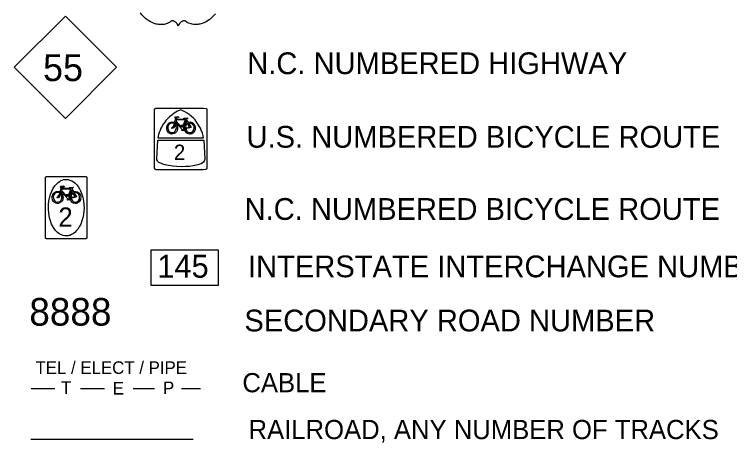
# Model space of a CAD drawing. Extents: x 5197761 to 5514561, y 1890130 to 2080942.
# Drawn here: x 5485887 to 5504538, y 2029224 to 2040388 of the extents above; entities that cross this region are included whole.
import ezdxf

# ---------------------------------------------------------------- set-up
doc = ezdxf.new("R2010")
doc.units = 0
for name, color, linetype in [('Exist Railroad Mainline', 7, 'Continuous'), ('Exist Railroad Mainline Label', 7, 'Continuous'), ('Exist Road Primary Interstate Interchange CELL', 7, 'Continuous'), ('Exist Road Primary Interstate Label', 7, 'Continuous'), ('Exist Road Primary NC Shield Bike CELL', 7, 'Continuous'), ('Exist Road Primary NC Shield CELL', 7, 'Continuous'), ('Exist Road Primary NC Shield Number Label', 7, 'Continuous'), ('Exist Road Primary US Shield Bike CELL', 7, 'Continuous'), ('Exist Road Primary US Shield CELL', 7, 'Continuous'), ('Exist Road Primary US Shield Number Label', 7, 'Continuous'), ('Exist Road Secondary Type 51 Label', 7, 'Continuous'), ('Exist Road Secondary Type 51 Number Label', 7, 'Continuous'), ('Exist Utilities Electrical Transmission Line', 7, 'Continuous'), ('Exist Utilities Electrical Transmission Line Label', 7, 'Continuous')]:
    doc.layers.add(name, color=color, linetype=linetype)

msp = doc.modelspace()

# ---------------------------------------------------------------- linework, layer by layer
at = {"layer": 'Exist Railroad Mainline'}
msp.add_line((5490548, 2029308), (5486316, 2029308), dxfattribs=at)
at = {"layer": 'Exist Road Primary Interstate Interchange CELL'}
msp.add_lwpolyline([(5489459, 2034253), (5491199, 2034253), (5491199, 2033320), (5489459, 2033320)], close=True, dxfattribs=at)
at = {"layer": 'Exist Road Primary NC Shield Bike CELL'}
for points in [[(5486738, 2036164), (5486741, 2036164), (5486873, 2036164), (5487606, 2036164), (5487739, 2036164), (5487743, 2036163), (5487746, 2036163), (5487749, 2036162), (5487752, 2036161), (5487755, 2036160), (5487760, 2036158), (5487762, 2036156), (5487765, 2036154), (5487768, 2036152), (5487771, 2036148), (5487774, 2036145), (5487775, 2036143), (5487776, 2036141), (5487777, 2036139), (5487778, 2036138), (5487779, 2036136), (5487780, 2036133), (5487781, 2036129), (5487781, 2036126), (5487781, 2036124), (5487781, 2036123), (5487781, 2035989), (5487781, 2034709), (5487781, 2034577), (5487781, 2034572), (5487781, 2034570), (5487780, 2034567), (5487779, 2034564), (5487778, 2034561), (5487776, 2034556), (5487774, 2034553), (5487772, 2034551), (5487770, 2034548), (5487768, 2034546), (5487766, 2034544), (5487764, 2034543), (5487762, 2034541), (5487761, 2034540), (5487759, 2034540), (5487757, 2034538), (5487754, 2034537), (5487751, 2034536), (5487747, 2034535), (5487745, 2034535), (5487743, 2034534), (5487742, 2034534), (5487740, 2034534), (5487738, 2034534), (5487606, 2034534), (5486873, 2034534), (5486741, 2034534), (5486738, 2034534), (5486736, 2034534), (5486734, 2034535), (5486731, 2034535), (5486728, 2034536), (5486725, 2034537), (5486722, 2034539), (5486720, 2034540), (5486717, 2034541), (5486715, 2034543), (5486713, 2034544), (5486712, 2034546), (5486711, 2034547), (5486709, 2034549), (5486708, 2034550), (5486706, 2034552), (5486705, 2034554), (5486704, 2034556), (5486703, 2034558), (5486702, 2034560), (5486701, 2034562), (5486701, 2034563), (5486700, 2034564), (5486700, 2034565), (5486700, 2034566), (5486699, 2034567), (5486699, 2034568), (5486699, 2034569), (5486699, 2034570), (5486699, 2034571), (5486698, 2034572), (5486698, 2034573), (5486698, 2034574), (5486698, 2034576), (5486698, 2034709), (5486698, 2035989), (5486698, 2036121), (5486698, 2036126), (5486699, 2036128), (5486699, 2036131), (5486700, 2036134), (5486701, 2036137), (5486704, 2036142), (5486706, 2036145), (5486707, 2036147), (5486710, 2036150), (5486714, 2036154), (5486717, 2036156), (5486719, 2036157), (5486720, 2036158), (5486722, 2036159), (5486724, 2036160), (5486726, 2036161), (5486729, 2036162), (5486733, 2036163), (5486736, 2036163)], [(5487240, 2034612), (5487221, 2034613), (5487203, 2034614), (5487164, 2034621), (5487119, 2034638), (5487093, 2034650), (5487071, 2034662), (5487049, 2034678), (5487017, 2034701), (5486962, 2034757), (5486908, 2034829), (5486860, 2034922), (5486827, 2035005), (5486806, 2035087), (5486784, 2035210), (5486776, 2035308), (5486776, 2035355), (5486777, 2035390), (5486778, 2035415), (5486781, 2035452), (5486786, 2035509), (5486797, 2035568), (5486805, 2035605), (5486810, 2035626), (5486821, 2035665), (5486831, 2035699), (5486863, 2035781), (5486902, 2035855), (5486945, 2035917), (5486983, 2035964), (5487029, 2036007), (5487065, 2036031), (5487083, 2036042), (5487104, 2036053), (5487139, 2036069), (5487180, 2036080), (5487218, 2036086), (5487248, 2036086), (5487292, 2036082), (5487337, 2036070), (5487389, 2036047), (5487434, 2036019), (5487474, 2035986), (5487516, 2035942), (5487551, 2035897), (5487585, 2035841), (5487614, 2035787), (5487642, 2035718), (5487665, 2035646), (5487681, 2035577), (5487693, 2035511), (5487699, 2035453), (5487701, 2035420), (5487705, 2035344), (5487701, 2035263), (5487690, 2035168), (5487673, 2035086), (5487650, 2035002), (5487618, 2034922), (5487582, 2034851), (5487548, 2034799), (5487512, 2034753), (5487468, 2034706), (5487426, 2034673), (5487381, 2034647), (5487335, 2034627), (5487307, 2034620), (5487290, 2034617), (5487277, 2034614), (5487261, 2034613)], [(5487318, 2035871), (5487414, 2035882), (5487421, 2035875), (5487415, 2035860), (5487392, 2035853), (5487385, 2035840), (5487426, 2035771), (5487484, 2035774), (5487535, 2035762), (5487580, 2035728), (5487602, 2035694), (5487612, 2035675), (5487619, 2035644), (5487621, 2035612), (5487617, 2035577), (5487609, 2035551), (5487595, 2035524), (5487581, 2035503), (5487554, 2035481), (5487530, 2035467), (5487496, 2035459), (5487475, 2035458), (5487432, 2035465), (5487404, 2035479), (5487391, 2035490), (5487370, 2035516), (5487356, 2035540), (5487338, 2035589), (5487334, 2035613), (5487363, 2035591), (5487386, 2035552), (5487403, 2035525), (5487424, 2035510), (5487457, 2035496), (5487481, 2035496), (5487514, 2035503), (5487544, 2035520), (5487566, 2035542), (5487583, 2035570), (5487589, 2035610), (5487588, 2035643), (5487580, 2035670), (5487566, 2035694), (5487552, 2035711), (5487528, 2035729), (5487505, 2035737), (5487468, 2035744), (5487442, 2035747), (5487512, 2035628), (5487363, 2035591), (5487334, 2035613), (5487470, 2035637), (5487413, 2035735), (5487374, 2035693), (5487363, 2035619), (5487334, 2035613), (5487335, 2035644), (5487348, 2035691), (5487369, 2035724), (5487400, 2035760), (5487381, 2035802), (5487306, 2035610), (5487334, 2035613), (5487338, 2035589), (5487304, 2035585), (5487311, 2035564), (5487332, 2035553), (5487281, 2035542), (5487269, 2035558), (5487287, 2035567), (5487108, 2035772), (5487101, 2035752), (5487126, 2035719), (5487143, 2035687), (5487154, 2035653), (5487159, 2035623), (5487156, 2035593), (5487148, 2035553), (5487128, 2035518), (5487101, 2035491), (5487070, 2035472), (5487031, 2035462), (5487003, 2035460), (5486975, 2035464), (5486926, 2035494), (5486910, 2035512), (5486887, 2035553), (5486877, 2035605), (5486876, 2035642), (5486886, 2035675), (5486900, 2035704), (5486917, 2035725), (5486941, 2035749), (5486962, 2035762), (5486990, 2035771), (5487018, 2035773), (5487079, 2035767), (5487093, 2035734), (5487074, 2035658), (5487050, 2035618), (5487015, 2035601), (5487001, 2035615), (5487058, 2035673), (5487070, 2035728), (5487057, 2035734), (5487033, 2035742), (5486995, 2035743), (5486973, 2035736), (5486944, 2035719), (5486915, 2035682), (5486903, 2035643), (5486908, 2035600), (5486919, 2035560), (5486933, 2035535), (5486953, 2035519), (5486982, 2035501), (5487008, 2035496), (5487040, 2035499), (5487071, 2035512), (5487098, 2035539), (5487115, 2035572), (5487125, 2035595), (5487128, 2035624), (5487124, 2035656), (5487109, 2035692), (5487079, 2035767), (5487110, 2035854), (5487131, 2035831), (5487120, 2035797), (5487262, 2035637), (5487258, 2035657), (5487243, 2035683), (5487250, 2035689), (5487291, 2035689), (5487283, 2035659), (5487287, 2035638), (5487363, 2035829), (5487131, 2035831), (5487110, 2035854), (5487083, 2035882), (5487106, 2035909), (5487167, 2035917), (5487192, 2035897), (5487179, 2035880), (5487141, 2035884), (5487116, 2035879), (5487122, 2035874), (5487135, 2035874), (5487129, 2035861), (5487366, 2035859), (5487367, 2035864)]]:
    msp.add_lwpolyline(points, close=True, dxfattribs=at)
at = {"layer": 'Exist Road Primary NC Shield CELL'}
msp.add_lwpolyline([(5485887, 2039007), (5487219, 2040339), (5488551, 2039007), (5487219, 2037675)], close=True, dxfattribs=at)
at = {"layer": 'Exist Road Primary US Shield Bike CELL'}
for points in [[(5489583, 2037942), (5489587, 2037942), (5489938, 2037942), (5490672, 2037942), (5490804, 2037942), (5490808, 2037942), (5490811, 2037941), (5490814, 2037941), (5490817, 2037940), (5490820, 2037939), (5490887, 2037936), (5490889, 2037935), (5490891, 2037933), (5490894, 2037930), (5490898, 2037926), (5490901, 2037923), (5490902, 2037921), (5490902, 2037920), (5490904, 2037918), (5490904, 2037916), (5490905, 2037914), (5490906, 2037911), (5490907, 2037908), (5490908, 2037904), (5490908, 2037903), (5490908, 2037901), (5490908, 2037767), (5490908, 2036488), (5490908, 2036382), (5490908, 2036377), (5490907, 2036375), (5490907, 2036372), (5490906, 2036369), (5490905, 2036366), (5490902, 2036360), (5490901, 2036358), (5490899, 2036356), (5490896, 2036353), (5490895, 2036351), (5490892, 2036349), (5490891, 2036348), (5490889, 2036346), (5490887, 2036345), (5490874, 2036340), (5490809, 2036339), (5490807, 2036339), (5490805, 2036339), (5490803, 2036339), (5490671, 2036339), (5489938, 2036339), (5489587, 2036339), (5489584, 2036339), (5489582, 2036339), (5489579, 2036340), (5489576, 2036340), (5489573, 2036341), (5489571, 2036342), (5489568, 2036344), (5489565, 2036345), (5489563, 2036346), (5489560, 2036348), (5489559, 2036349), (5489557, 2036351), (5489556, 2036352), (5489555, 2036354), (5489553, 2036355), (5489552, 2036357), (5489551, 2036359), (5489550, 2036360), (5489548, 2036363), (5489547, 2036365), (5489547, 2036367), (5489546, 2036368), (5489546, 2036369), (5489545, 2036370), (5489545, 2036371), (5489545, 2036372), (5489545, 2036373), (5489544, 2036374), (5489544, 2036375), (5489544, 2036376), (5489544, 2036377), (5489544, 2036378), (5489544, 2036379), (5489544, 2036381), (5489544, 2036487), (5489544, 2037767), (5489544, 2037899), (5489544, 2037904), (5489544, 2037906), (5489545, 2037909), (5489546, 2037912), (5489547, 2037915), (5489550, 2037921), (5489551, 2037923), (5489553, 2037925), (5489555, 2037928), (5489559, 2037932), (5489563, 2037935), (5489564, 2037936), (5489566, 2037936), (5489568, 2037938), (5489570, 2037938), (5489571, 2037939), (5489574, 2037940), (5489578, 2037941), (5489582, 2037942)], [(5490226, 2037902), (5490143, 2037865), (5490058, 2037812), (5489990, 2037762), (5489937, 2037720), (5489883, 2037665), (5489840, 2037617), (5489808, 2037577), (5489771, 2037521), (5489728, 2037449), (5489710, 2037417), (5489686, 2037357), (5489666, 2037307), (5489650, 2037256), (5489630, 2037170), (5490821, 2037170), (5490809, 2037221), (5490792, 2037287), (5490761, 2037370), (5490739, 2037418), (5490693, 2037503), (5490647, 2037572), (5490598, 2037634), (5490558, 2037678), (5490508, 2037726), (5490448, 2037776), (5490390, 2037816), (5490337, 2037848), (5490281, 2037876), (5490262, 2037885)], [(5490303, 2037679), (5490399, 2037690), (5490406, 2037683), (5490401, 2037668), (5490377, 2037661), (5490371, 2037648), (5490411, 2037579), (5490469, 2037582), (5490521, 2037571), (5490566, 2037536), (5490587, 2037502), (5490597, 2037484), (5490604, 2037453), (5490606, 2037420), (5490602, 2037386), (5490595, 2037360), (5490580, 2037332), (5490566, 2037312), (5490539, 2037290), (5490515, 2037276), (5490481, 2037267), (5490460, 2037266), (5490417, 2037273), (5490389, 2037287), (5490376, 2037298), (5490355, 2037324), (5490342, 2037349), (5490323, 2037397), (5490319, 2037421), (5490348, 2037400), (5490372, 2037360), (5490388, 2037333), (5490410, 2037318), (5490442, 2037305), (5490467, 2037304), (5490499, 2037312), (5490529, 2037329), (5490551, 2037350), (5490568, 2037378), (5490574, 2037419), (5490573, 2037451), (5490566, 2037478), (5490552, 2037503), (5490537, 2037520), (5490513, 2037538), (5490490, 2037545), (5490453, 2037552), (5490427, 2037555), (5490497, 2037437), (5490348, 2037400), (5490319, 2037421), (5490456, 2037446), (5490399, 2037543), (5490359, 2037501), (5490348, 2037427), (5490319, 2037421), (5490320, 2037452), (5490333, 2037499), (5490355, 2037532), (5490386, 2037568), (5490366, 2037610), (5490291, 2037418), (5490319, 2037421), (5490323, 2037397), (5490289, 2037393), (5490297, 2037373), (5490317, 2037362), (5490267, 2037350), (5490254, 2037366), (5490272, 2037376), (5490093, 2037580), (5490087, 2037561), (5490112, 2037527), (5490128, 2037495), (5490139, 2037461), (5490145, 2037431), (5490142, 2037401), (5490133, 2037362), (5490114, 2037326), (5490086, 2037299), (5490055, 2037280), (5490017, 2037271), (5489989, 2037268), (5489960, 2037272), (5489911, 2037302), (5489895, 2037320), (5489872, 2037362), (5489862, 2037413), (5489862, 2037450), (5489871, 2037483), (5489886, 2037512), (5489902, 2037533), (5489927, 2037557), (5489948, 2037571), (5489975, 2037579), (5490003, 2037582), (5490064, 2037575), (5490078, 2037542), (5490060, 2037466), (5490035, 2037426), (5490000, 2037410), (5489986, 2037424), (5490043, 2037482), (5490056, 2037537), (5490043, 2037542), (5490019, 2037550), (5489980, 2037551), (5489959, 2037545), (5489929, 2037527), (5489901, 2037490), (5489888, 2037451), (5489893, 2037409), (5489904, 2037369), (5489918, 2037343), (5489938, 2037327), (5489967, 2037309), (5489993, 2037305), (5490026, 2037307), (5490057, 2037320), (5490084, 2037347), (5490101, 2037380), (5490111, 2037403), (5490113, 2037433), (5490109, 2037464), (5490094, 2037500), (5490064, 2037575), (5490095, 2037662), (5490117, 2037639), (5490105, 2037605), (5490247, 2037446), (5490251, 2037458), (5490247, 2037473), (5490231, 2037483), (5490235, 2037497), (5490276, 2037497), (5490268, 2037468), (5490272, 2037447), (5490348, 2037638), (5490117, 2037639), (5490095, 2037662), (5490069, 2037690), (5490091, 2037717), (5490153, 2037725), (5490177, 2037706), (5490164, 2037689), (5490145, 2037707), (5490114, 2037700), (5490101, 2037687), (5490107, 2037682), (5490120, 2037682), (5490110, 2037658), (5490350, 2037654), (5490357, 2037671), (5490304, 2037673)], [(5489632, 2037107), (5490827, 2037107), (5490850, 2036613), (5490846, 2036588), (5490836, 2036559), (5490817, 2036538), (5490797, 2036517), (5490760, 2036494), (5490725, 2036482), (5490671, 2036463), (5490636, 2036456), (5490548, 2036439), (5490454, 2036425), (5490353, 2036421), (5490245, 2036417), (5490126, 2036421), (5490017, 2036428), (5489909, 2036446), (5489823, 2036464), (5489761, 2036484), (5489724, 2036498), (5489676, 2036517), (5489655, 2036530), (5489630, 2036553), (5489616, 2036574), (5489607, 2036599), (5489603, 2036624)]]:
    msp.add_lwpolyline(points, close=True, dxfattribs=at)
at = {"layer": 'Exist Road Primary US Shield CELL'}
msp.add_lwpolyline([(5491128, 2040404), (5491102, 2040372), (5491071, 2040337), (5491046, 2040312), (5491012, 2040282), (5490992, 2040266), (5490964, 2040244), (5490925, 2040218), (5490886, 2040196), (5490853, 2040179), (5490824, 2040166), (5490786, 2040152), (5490724, 2040135), (5490701, 2040130), (5490674, 2040126), (5490648, 2040123), (5490624, 2040122), (5490590, 2040122), (5490558, 2040124), (5490526, 2040129), (5490494, 2040136), (5490460, 2040146), (5490429, 2040158), (5490398, 2040173), (5490346, 2040206), (5490330, 2040214), (5490322, 2040216), (5490302, 2040217), (5490283, 2040213), (5490263, 2040206), (5490251, 2040199), (5490235, 2040189), (5490223, 2040179), (5490209, 2040166), (5490199, 2040154), (5490191, 2040145), (5490176, 2040122), (5490171, 2040111), (5490166, 2040096), (5490161, 2040075), (5490154, 2040102), (5490146, 2040119), (5490137, 2040135), (5490128, 2040148), (5490113, 2040165), (5490100, 2040178), (5490084, 2040191), (5490066, 2040201), (5490053, 2040208), (5490040, 2040213), (5490025, 2040217), (5490012, 2040218), (5490002, 2040217), (5489988, 2040214), (5489969, 2040200), (5489950, 2040188), (5489931, 2040175), (5489907, 2040163), (5489890, 2040155), (5489869, 2040147), (5489845, 2040139), (5489819, 2040132), (5489792, 2040127), (5489768, 2040123), (5489743, 2040121), (5489720, 2040120), (5489696, 2040120), (5489674, 2040122), (5489648, 2040124), (5489616, 2040129), (5489589, 2040135), (5489561, 2040143), (5489532, 2040152), (5489502, 2040163), (5489463, 2040180), (5489436, 2040194), (5489394, 2040218), (5489344, 2040253), (5489306, 2040283), (5489279, 2040308), (5489238, 2040349), (5489215, 2040376), (5489177, 2040424)], dxfattribs=at)
at = {"layer": 'Exist Utilities Electrical Transmission Line'}
for p, q in [((5486328, 2030638), (5486946, 2030638)), ((5487610, 2030638), (5488236, 2030638)), ((5488989, 2030638), (5489546, 2030638)), ((5490250, 2030638), (5490737, 2030638))]:
    msp.add_line(p, q, dxfattribs=at)

# ---------------------------------------------------------------- texts
at = {"layer": 'Exist Railroad Mainline Label'}
msp.add_text('RAILROAD, ANY NUMBER OF TRACKS', height=500, dxfattribs=at).set_placement((5491994, 2029317))
at = {"layer": 'Exist Road Primary Interstate Interchange CELL'}
msp.add_text('145', height=600, dxfattribs=at).set_placement((5489616, 2033524))
at = {"layer": 'Exist Road Primary Interstate Label'}
msp.add_text('INTERSTATE INTERCHANGE NUMBER', height=567.41, dxfattribs=at).set_placement((5491980, 2033535))
at = {"layer": 'Exist Road Primary NC Shield Bike CELL'}
msp.add_text('2', height=500, dxfattribs=at).set_placement((5487037, 2034855))
at = {"layer": 'Exist Road Primary NC Shield Number Label'}
for s, height, p in [('55', 700, (5486636, 2038648)), ('N.C. NUMBERED HIGHWAY', 567.41, (5491960, 2038829)), ('N.C. NUMBERED BICYCLE ROUTE', 567.41, (5491891, 2035031))]:
    msp.add_text(s, height=height, dxfattribs=at).set_placement(p)
at = {"layer": 'Exist Road Primary US Shield Bike CELL'}
msp.add_text('2', height=400, dxfattribs=at).set_placement((5490046, 2036592))
at = {"layer": 'Exist Road Primary US Shield Number Label'}
msp.add_text('U.S. NUMBERED BICYCLE ROUTE', height=567.41, dxfattribs=at).set_placement((5491941, 2036912))
at = {"layer": 'Exist Road Secondary Type 51 Label'}
msp.add_text('SECONDARY ROAD NUMBER', height=567.41, dxfattribs=at).set_placement((5491886, 2032124))
at = {"layer": 'Exist Road Secondary Type 51 Number Label'}
msp.add_text('8888', height=720, dxfattribs=at).set_placement((5486278, 2032275))
at = {"layer": 'Exist Utilities Electrical Transmission Line'}
for s, height, p in [('TEL / ELECT / PIPE', 328.08, (5486439, 2031017)), ('T', 328, (5487104, 2030494)), ('E', 328, (5488453, 2030479)), ('P', 328, (5489763, 2030489))]:
    msp.add_text(s, height=height, rotation=359.98, dxfattribs=at).set_placement(p)
at = {"layer": 'Exist Utilities Electrical Transmission Line Label'}
msp.add_text('CABLE', height=500, dxfattribs=at).set_placement((5491833, 2030538))

doc.saveas('drawing.dxf')
